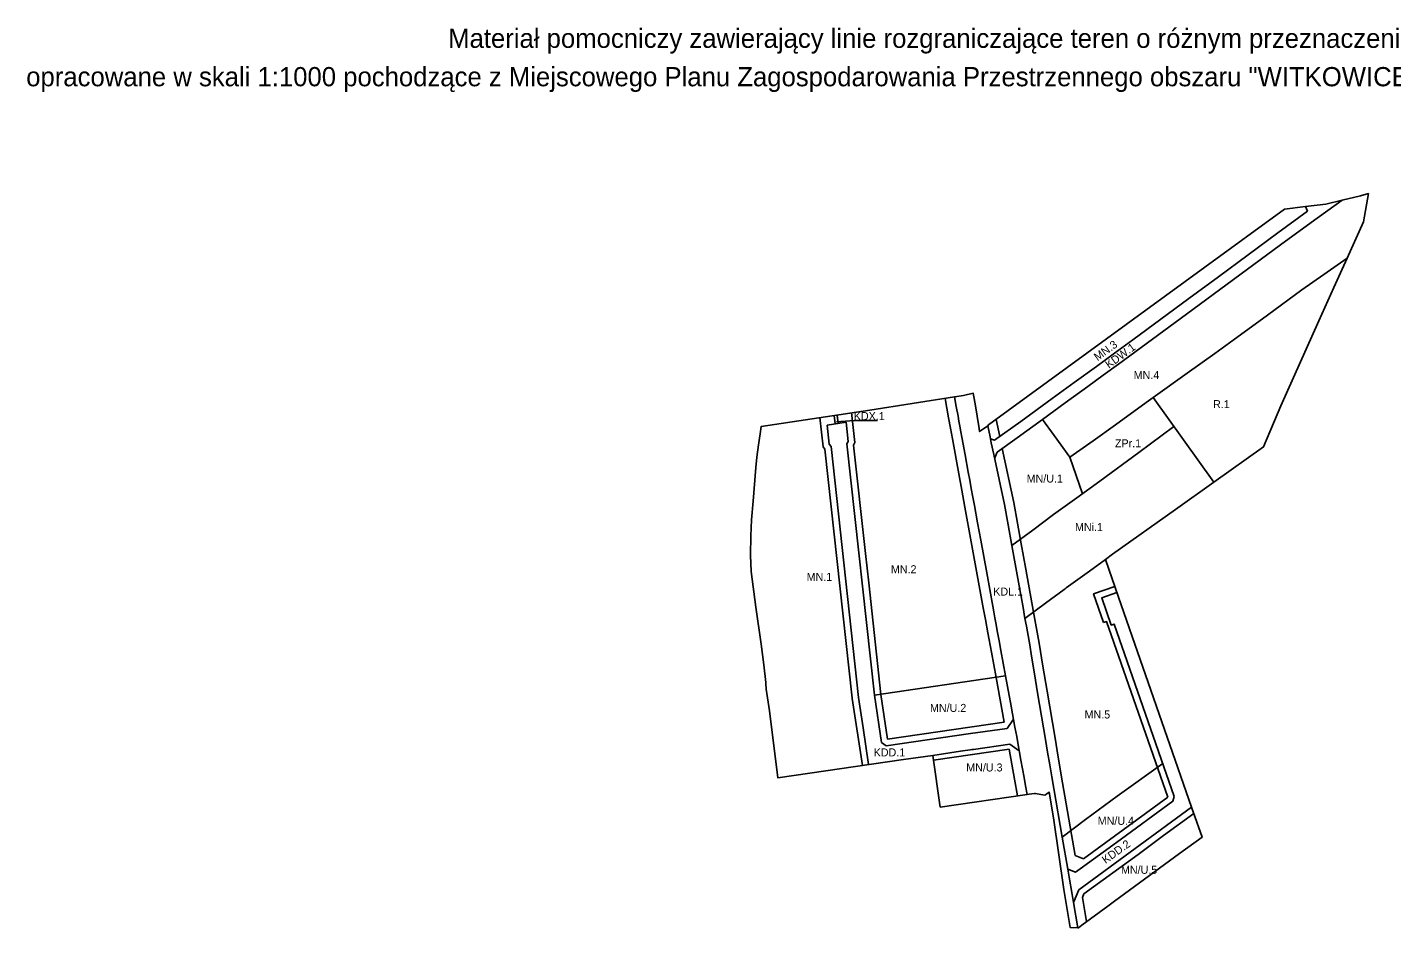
# Model space of a CAD drawing. Extents: x 7423729 to 7425180, y 5553738 to 5554301.
import ezdxf

# ---------------------------------------------------------------- set-up
doc = ezdxf.new("R2010")
doc.units = 0
for name, color, linetype in [('info', 7, 'Continuous'), ('linie rozgraniczające', 7, 'Continuous'), ('nieprzekraczalne linie zabudowy', 7, 'Continuous'), ('przeznaczenia terenów', 7, 'Continuous')]:
    doc.layers.add(name, color=color, linetype=linetype)

msp = doc.modelspace()

# ---------------------------------------------------------------- linework, layer by layer
at = {"layer": 'linie rozgraniczające'}
for p, q in [((7424432.29, 5554069.58), (7424470.2, 5554016.76)), ((7424232.98, 5554058.32), (7424233.56, 5554053.1)), ((7424234.96, 5554058.62), (7424235.53, 5554053.4)), ((7424228.61, 5554052.37), (7424240.48, 5554054.13)), ((7424228.61, 5554052.37), (7424229.92, 5554040.43)), ((7424240.48, 5554054.13), (7424241.76, 5554042.19)), ((7424330.38, 5554044.94), (7424328.89, 5554051.99)), ((7424231.07, 5554039.09), (7424229.92, 5554040.43)), ((7424240.96, 5554040.57), (7424241.76, 5554042.19)), ((7424340.04, 5553895.82), (7424258.17, 5553883.72)), ((7424262.6, 5553854.05), (7424258.17, 5553883.72)), ((7424265.44, 5553851.94), (7424262.6, 5553854.05))]:
    msp.add_line(p, q, dxfattribs=at)
msp.add_lwpolyline([(7424328.89, 5554051.99), (7424329.5, 5554052.43), (7424464.52, 5554151), (7424514.22, 5554187.27), (7424527.52, 5554188.9), (7424540.14, 5554190.44), (7424550.33, 5554192.9), (7424561.71, 5554195.64), (7424566.79, 5554196.93), (7424563.59, 5554179.29), (7424553.47, 5554156.7), (7424545.17, 5554138.29), (7424535.8, 5554117.46), (7424511.99, 5554064.34), (7424501.3, 5554038.78), (7424470.2, 5554016.76), (7424446.13, 5553999.72), (7424406.95, 5553971.72), (7424402.4, 5553968.41), (7424410.58, 5553944.91), (7424456.29, 5553813.61), (7424462.81, 5553794.88), (7424448.65, 5553784.79), (7424408.06, 5553755.01), (7424403.92, 5553751.88), (7424387.8, 5553740.06), (7424385.56, 5553738.42), (7424385.29, 5553738.42), (7424380.51, 5553738.48), (7424376.41, 5553762.38), (7424369.92, 5553807.08), (7424367.29, 5553823.11), (7424365.78, 5553821.97), (7424364.66, 5553821.12), (7424358.64, 5553822.33), (7424358.05, 5553822.24), (7424354.74, 5553821.77), (7424353.5, 5553821.59), (7424299.21, 5553813.75), (7424294.54, 5553846.07), (7424276.21, 5553843.4), (7424197.72, 5553832.04), (7424192.55, 5553873.92), (7424190.6, 5553887.5), (7424190.4, 5553891.01), (7424190.34, 5553891.5), (7424190.34, 5553891.51), (7424188.99, 5553902.62), (7424188.19, 5553909.17), (7424187.42, 5553915.53), (7424184.1, 5553938.65), (7424181.1, 5553960.82), (7424180.64, 5553971.18), (7424180.99, 5553983.12), (7424181.42, 5553993.11), (7424182.47, 5554004.8), (7424183.98, 5554025.95), (7424184.65, 5554032.39), (7424185.75, 5554039.94), (7424186.73, 5554046.82), (7424187.4, 5554051.54), (7424255.29, 5554061.64), (7424308.19, 5554070.02), (7424308.24, 5554070.03), (7424313.84, 5554070.92), (7424319.92, 5554072.24), (7424320.29, 5554070.1), (7424321.05, 5554065.59), (7424323.48, 5554050.15), (7424323.78, 5554048.26)], close=True, dxfattribs=at)
for points in [[(7424333.24, 5554031.45), (7424334.75, 5554035.36), (7424347.27, 5554044.42), (7424363.18, 5554055.94), (7424377.33, 5554066.2), (7424391.48, 5554076.46), (7424401.07, 5554083.46), (7424410.65, 5554090.46), (7424431.92, 5554106.05), (7424453.2, 5554121.65), (7424482.5, 5554143.29), (7424511.81, 5554164.92), (7424531.08, 5554178.92), (7424550.33, 5554192.9)], [(7424330.62, 5554043.83), (7424333.16, 5554042.85), (7424349.53, 5554054.7), (7424369.12, 5554068.88), (7424382.96, 5554078.95), (7424396.79, 5554089.01), (7424408.16, 5554097.32), (7424419.52, 5554105.62), (7424437.06, 5554118.49), (7424454.6, 5554131.36), (7424473.12, 5554145.04), (7424491.63, 5554158.72), (7424510.15, 5554172.4), (7424528.66, 5554186.07), (7424527.52, 5554188.9)], [(7424388.12, 5554009.46), (7424380.14, 5554032.37), (7424394.69, 5554042.56), (7424408.66, 5554052.59), (7424427.92, 5554066.45), (7424432.29, 5554069.58), (7424453.49, 5554084.76), (7424470.82, 5554097.16), (7424482.28, 5554105.35), (7424503.72, 5554121.08), (7424525.16, 5554136.81), (7424538.96, 5554146.51), (7424553.47, 5554156.7)], [(7424353.5, 5553821.59), (7424352.54, 5553826.94), (7424351.58, 5553832.28), (7424349.66, 5553843.05), (7424347.73, 5553853.83), (7424347.01, 5553857.76), (7424345.93, 5553863.67), (7424343.53, 5553876.79), (7424340.04, 5553895.82), (7424338.59, 5553903.71), (7424337.15, 5553911.61), (7424336.04, 5553917.69), (7424334.92, 5553923.77), (7424334.17, 5553927.9), (7424333.41, 5553932.03), (7424332.74, 5553935.67), (7424332.07, 5553939.32), (7424330.17, 5553949.73), (7424328.26, 5553960.14), (7424326.39, 5553970.36), (7424324.52, 5553980.58), (7424322.56, 5553991.33), (7424320.6, 5554002.08), (7424319.62, 5554007.44), (7424318.64, 5554012.8), (7424317.71, 5554017.9), (7424316.77, 5554022.99), (7424314.79, 5554033.88), (7424312.8, 5554044.77), (7424312.17, 5554048.2), (7424311.55, 5554051.62), (7424310.97, 5554054.79), (7424310.39, 5554057.96), (7424309.29, 5554063.99), (7424308.19, 5554070.02)], [(7424445.24, 5554051.55), (7424423.25, 5554035.24), (7424399.02, 5554017.27), (7424384.55, 5554006.91), (7424370.08, 5553996.54), (7424357.04, 5553986.83), (7424344, 5553977.13)], [(7424380.14, 5554032.37), (7424370.47, 5554045.81), (7424363.18, 5554055.94)], [(7424258.17, 5553883.72), (7424258.17, 5553883.73), (7424240.96, 5554040.57)], [(7424370.24, 5553825.34), (7424368.93, 5553832.73), (7424367.62, 5553840.12), (7424366.36, 5553848), (7424365.09, 5553855.89), (7424362.59, 5553870.54), (7424360.1, 5553885.19), (7424358.78, 5553893), (7424357.45, 5553900.8), (7424356.31, 5553907.93), (7424355.17, 5553915.06), (7424353.69, 5553923.33), (7424353.08, 5553926.67), (7424352.2, 5553931.59), (7424350.96, 5553938.42), (7424349.73, 5553945.24), (7424349.33, 5553947.46), (7424346.87, 5553961.19), (7424344, 5553977.13), (7424341.65, 5553990), (7424339.3, 5554002.87), (7424332.72, 5554033.9), (7424331.14, 5554041.38), (7424330.38, 5554044.94)], [(7424248.28, 5553882.25), (7424231.07, 5554039.09)], [(7424402.4, 5553968.41), (7424392.48, 5553961.19), (7424378.01, 5553950.66), (7424377.3, 5553950.14), (7424376.65, 5553949.66), (7424365.11, 5553941.12), (7424352.2, 5553931.59)], [(7424445.49, 5553820.3), (7424407.96, 5553928.12), (7424406.07, 5553927.46), (7424400.15, 5553944.46), (7424409.6, 5553947.75)], [(7424254.54, 5553840.26), (7424251.12, 5553863.25), (7424248.28, 5553882.25)], [(7424265.44, 5553851.94), (7424318.2, 5553859.63), (7424340.98, 5553862.95), (7424345.03, 5553868.59)], [(7424294.54, 5553846.07), (7424311.97, 5553848.62), (7424318.02, 5553849.5), (7424319.01, 5553849.64), (7424320, 5553849.79), (7424342.78, 5553853.11), (7424348.61, 5553848.91)], [(7424438.29, 5553840.99), (7424409.78, 5553820.59), (7424390.06, 5553805.95), (7424375.48, 5553795.04)], [(7424385.29, 5553738.42), (7424382.56, 5553754.16), (7424381.71, 5553759.08), (7424379.81, 5553770.08), (7424378.95, 5553775), (7424375.48, 5553795.04), (7424370.24, 5553825.34)], [(7424445.49, 5553820.3), (7424444.6, 5553817.44), (7424409.28, 5553791.63), (7424386.73, 5553775.14), (7424383.84, 5553773.03), (7424378.95, 5553775)], [(7424456.29, 5553813.61), (7424385.75, 5553762.03), (7424382.56, 5553754.16)]]:
    msp.add_lwpolyline(points, dxfattribs=at)
at = {"layer": 'nieprzekraczalne linie zabudowy'}
for p, q in [((7424250.59, 5553839.69), (7424244.32, 5553881.66)), ((7424250.59, 5553839.69), (7424244.32, 5553881.66)), ((7424266.34, 5553856.11), (7424339.27, 5553866.74)), ((7424342.32, 5553849.99), (7424294.98, 5553843.08)), ((7424389.03, 5553759.48), (7424388.12, 5553757.23))]:
    msp.add_line(p, q, dxfattribs=at)
for points in [[(7424339.27, 5553866.74), (7424334.14, 5553894.74), (7424331.25, 5553910.53), (7424329.02, 5553922.69), (7424327.51, 5553930.95), (7424326.17, 5553938.24), (7424318.62, 5553979.5), (7424314.7, 5554001), (7424312.74, 5554011.72), (7424310.87, 5554021.91), (7424306.9, 5554043.69), (7424305.65, 5554050.54), (7424304.49, 5554056.88), (7424302.26, 5554069.08)], [(7424227.23, 5554037.42), (7424226.08, 5554038.77), (7424224.06, 5554057.15)], [(7424243.85, 5554060.18), (7424245.86, 5554041.46), (7424245.06, 5554039.84)], [(7424334.2, 5554055.87), (7424336.46, 5554045.23)], [(7424245.06, 5554039.84), (7424252.5, 5553972.09), (7424254.69, 5553953.76), (7424262.15, 5553884.16), (7424264.23, 5553870.21), (7424266.34, 5553856.11)], [(7424244.3, 5553881.81), (7424227.23, 5554037.42)], [(7424338.04, 5554037.75), (7424345.19, 5554004.03), (7424349.9, 5553978.2), (7424352.77, 5553962.27), (7424357.58, 5553935.57)], [(7424401.31, 5553928.98), (7424395.06, 5553946.92), (7424408.28, 5553951.53)], [(7424357.58, 5553935.57), (7424361.09, 5553916.06), (7424363.37, 5553901.78), (7424366.02, 5553886.2), (7424371.01, 5553856.87), (7424372.27, 5553848.99), (7424374.84, 5553833.75), (7424383.56, 5553783.56)], [(7424441.35, 5553820.02), (7424403.2, 5553929.64), (7424401.31, 5553928.98)], [(7424347.56, 5553820.73), (7424345.67, 5553831.22), (7424342.32, 5553849.99)], [(7424388.66, 5553781.51), (7424441.35, 5553820.02)], [(7424457.67, 5553809.66), (7424438.78, 5553795.92), (7424422.9, 5553784.24), (7424422.9, 5553784.24), (7424389.03, 5553759.48)], [(7424383.56, 5553783.56), (7424388.66, 5553781.51)], [(7424389.03, 5553759.48), (7424388.12, 5553757.23), (7424390.72, 5553742.2)]]:
    msp.add_lwpolyline(points, dxfattribs=at)
at = {"layer": 'przeznaczenia terenów'}
msp.add_lwpolyline([(7424260.02, 5554055.32), (7424245.45, 5554055.32), (7424234.35, 5554054.46)], dxfattribs=at)

# ---------------------------------------------------------------- texts
at = {"layer": 'info'}
for s, p in [('Materiał pomocniczy zawierający linie rozgraniczające teren o różnym przeznaczeniu i różnych warunkach zagospodarowania terenu, ', (7423991.84, 5554288)), ('opracowane w skali 1:1000 pochodzące z Miejscowego Planu Zagospodarowania Przestrzennego obszaru "WITKOWICE - PÓŁNOC" zatwierdzonego uchwałą RMK Nr VI/112/19 z dnia 30 stycznia 2019 r.', (7423728.24, 5554264))]:
    msp.add_text(s, height=12, dxfattribs=at).set_placement(p)
at = {"layer": 'przeznaczenia terenów'}
for s, rotation, p in [('MN.3', 35.89943, (7424397.51, 5554092.24)), ('KDW.1', 36.33214, (7424404.69, 5554087.45)), ('KDD.2', 35.59858, (7424402.52, 5553778.15))]:
    msp.add_text(s, height=5, rotation=rotation, dxfattribs=at).set_placement(p)
for s, p in [('MN.4', (7424420.1, 5554081.12)), ('R.1', (7424469.69, 5554062.95)), ('KDX.1', (7424245.25, 5554055.51)), ('ZPr.1', (7424408.39, 5554038.47)), ('MN/U.1', (7424353.24, 5554016.5)), ('MNi.1', (7424383.45, 5553986.19)), ('MN.2', (7424268.45, 5553959.84)), ('MN.1', (7424215.79, 5553955.08)), ('KDL.1', (7424332.37, 5553945.88)), ('MN/U.2', (7424292.84, 5553873.21)), ('MN.5', (7424389.43, 5553869.1)), ('KDD.1', (7424257.66, 5553845.42)), ('MN/U.3', (7424315.51, 5553836.02)), ('MN/U.4', (7424397.64, 5553802.68)), ('MN/U.5', (7424412.17, 5553772.09))]:
    msp.add_text(s, height=5, dxfattribs=at).set_placement(p)

doc.saveas('drawing.dxf')
